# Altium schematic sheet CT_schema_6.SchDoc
size 277 x 170 mm
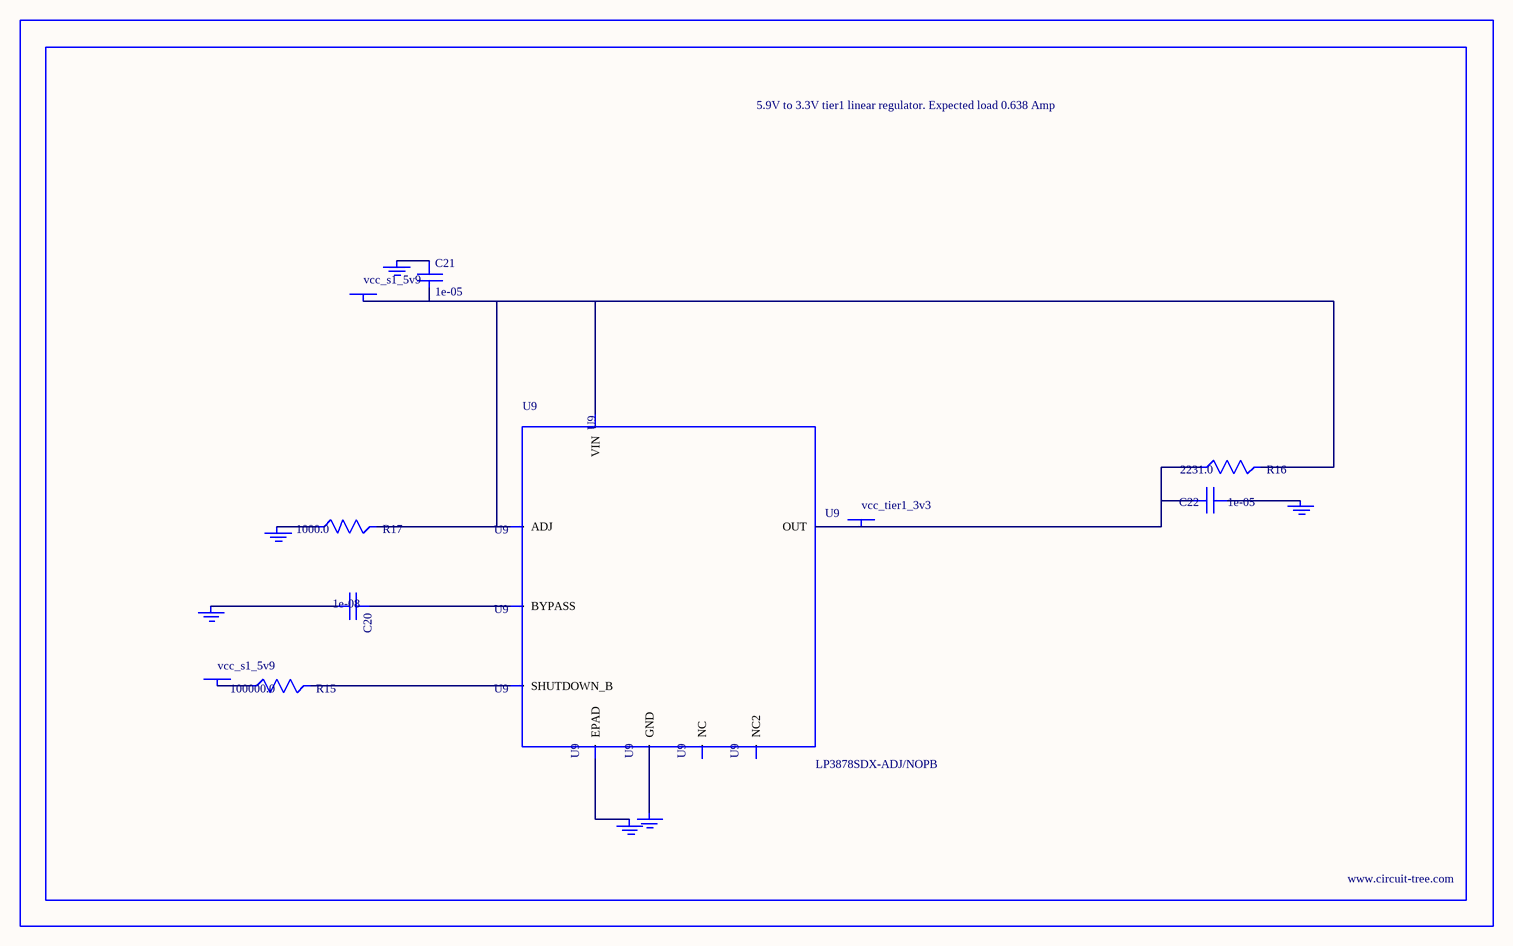
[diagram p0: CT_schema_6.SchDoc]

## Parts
BORDER5  (no value)
C20  1e-08  [C0402]
C21  1e-05  [C1206]
C22  1e-05  [C1210]
GND_INSTANCE_5_0  (no value)
GND_INSTANCE_5_1  (no value)
GND_INSTANCE_5_2  (no value)
GND_INSTANCE_5_3  (no value)
GND_INSTANCE_5_4  (no value)
GND_INSTANCE_5_5  (no value)
POWER_INSTANCE_5_0  vcc_s1_5v9
POWER_INSTANCE_5_1  vcc_s1_5v9
POWER_INSTANCE_5_2  vcc_tier1_3v3
R15  100000.0  [R0603]
R16  2231.0  [R0603]
R17  1000.0  [R0603]
U9  LP3878SDX-ADJ/NOPB  [WSON-8]

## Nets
NetC20_1: C20.1 U9.1(BYPASS)
NetC20_2: C20.2 GND_INSTANCE_5_0.0(GND)
NetC21_1: C21.1 GND_INSTANCE_5_1.0(GND)
NetC21_2: C21.2 POWER_INSTANCE_5_0.0(PWR) R16.2 R17.2 U9.4(VIN) U9.6(ADJ)
NetC22_1: C22.1 GND_INSTANCE_5_2.0(GND)
NetC22_2: C22.2 POWER_INSTANCE_5_2.0(PWR) R16.1 U9.5(OUT)
NetGND_INSTANCE_5_3_0: GND_INSTANCE_5_3.0(GND) R17.1
NetGND_INSTANCE_5_4_0: GND_INSTANCE_5_4.0(GND) U9.PAD(EPAD)
NetGND_INSTANCE_5_5_0: GND_INSTANCE_5_5.0(GND) U9.3(GND)
NetPOWER_INSTANCE_5_1_0: POWER_INSTANCE_5_1.0(PWR) R15.1
NetR15_2: R15.2 U9.8(SHUTDOWN_B)

Not connected (* = marked no-connect by the designer): U9 2(NC) 7(NC2)

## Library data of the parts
BORDER5 = BORDER_PAGE5
C20 = C0402C103K3RAC
C21 = C1206C106K3RACTU
C22 = GRM32DR61E106MA12L
GND_INSTANCE_5_0-GND_INSTANCE_5_5 = GND
POWER_INSTANCE_5_0-POWER_INSTANCE_5_2 = PWR
R15 = RC0603JR-07100KL
R16 = R16
R17 = RC0603JR-071KL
